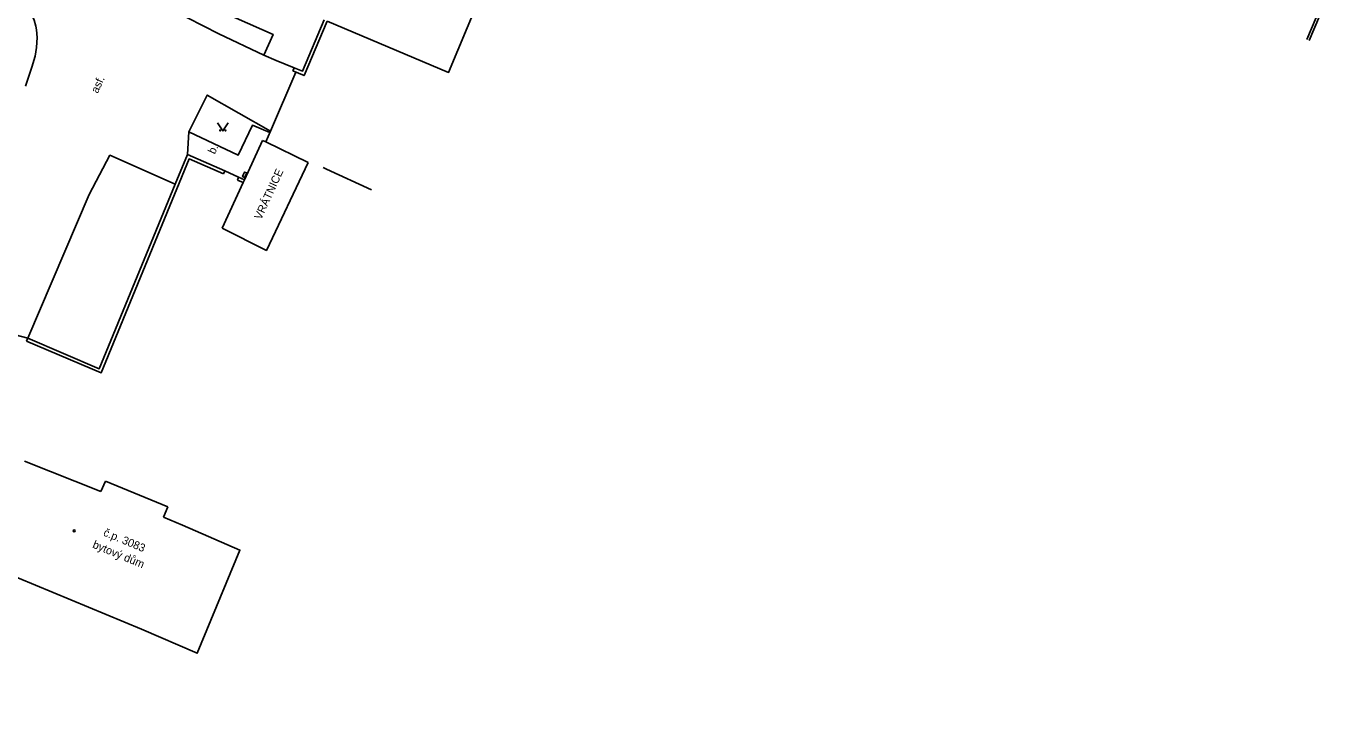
# Model space of a CAD drawing. Extents: x -584400 to -581602, y -1210894 to -1208793.
# Drawn here: x -582383.4 to -582261.2, y -1210133.9 to -1210069.5 of the extents above; entities that cross this region are included whole.
import ezdxf

# ---------------------------------------------------------------- set-up
doc = ezdxf.new("R2010")
doc.units = 0
for name, color, linetype in [('BUDOVY_MĚŘ', 7, 'Continuous'), ('BUDOVY_NEMĚŘ', 7, 'Continuous'), ('OBVOD_PILÍŘE', 7, 'Continuous'), ('POMOC_POPIS', 7, 'Continuous'), ('ROZHRANÍ_PLOCH', 7, 'Continuous'), ('ZN_BUDOV', 7, 'Continuous'), ('ZN_DOPLŇKOVÉ', 7, 'Continuous'), ('ZN_KULTUR', 7, 'Continuous'), ('Č_POPIS_ORIENT', 7, 'Continuous')]:
    doc.layers.add(name, color=color, linetype=linetype)

msp = doc.modelspace()

# ---------------------------------------------------------------- linework, layer by layer
at = {"layer": 'BUDOVY_MĚŘ'}
for points in [[(-582361.22, -1210080.25), (-582362.91, -1210083.93), (-582363.04, -1210084.2), (-582365, -1210088.47)], [(-582361.22, -1210080.25), (-582360.91, -1210080.39), (-582356.96, -1210082.32)], [(-582355.54, -1210082.79), (-582355.23, -1210082.93), (-582351, -1210084.89)], [(-582383.54, -1210110.3), (-582376.37, -1210113.14)], [(-582376.37, -1210113.14), (-582375.95, -1210112.16)], [(-582375.95, -1210112.16), (-582370.11, -1210114.57)], [(-582370.11, -1210114.57), (-582370.51, -1210115.56)], [(-582372.58, -1210126.03), (-582367.34, -1210128.3), (-582363.35, -1210118.64), (-582368.72, -1210116.31)], [(-582370.51, -1210115.56), (-582368.72, -1210116.31)], [(-582372.58, -1210126.03), (-582387.5, -1210119.87)]]:
    msp.add_lwpolyline(points, dxfattribs=at)
at = {"layer": 'BUDOVY_NEMĚŘ'}
for points in [[(-582324.28, -1210040.6), (-582328.11, -1210050.04), (-582332.42, -1210048.24), (-582334.79, -1210053.83), (-582335.37, -1210053.69), (-582343.78, -1210073.88), (-582355.17, -1210069.06)], [(-582365, -1210088.47), (-582360.86, -1210090.55), (-582356.96, -1210082.32)]]:
    msp.add_lwpolyline(points, dxfattribs=at)
at = {"layer": 'OBVOD_PILÍŘE'}
msp.add_lwpolyline([(-582363, -1210083.42), (-582362.9, -1210083.21), (-582362.7, -1210083.3), (-582362.9, -1210083.73), (-582363.1, -1210083.63), (-582363, -1210083.42)], dxfattribs=at)
at = {"layer": 'ROZHRANÍ_PLOCH'}
for points in [[(-582411.02, -1210050.39), (-582390.83, -1210062.64), (-582385.16, -1210066.13), (-582384.54, -1210066.56), (-582383.97, -1210067.05), (-582383.46, -1210067.6), (-582383.19, -1210067.95), (-582382.88, -1210068.44), (-582382.64, -1210068.97), (-582382.47, -1210069.53), (-582382.41, -1210069.88), (-582382.35, -1210070.59), (-582382.4, -1210071.54), (-582382.54, -1210072.35), (-582382.85, -1210073.38), (-582383.44, -1210075.16)], [(-582370.87, -1210063.26), (-582370.75, -1210064.68), (-582370.7, -1210065.22), (-582370.62, -1210065.6), (-582370.35, -1210066.42), (-582370.04, -1210067.13), (-582369.81, -1210067.51), (-582369.55, -1210067.81), (-582369.04, -1210068.25), (-582368.24, -1210068.77), (-582365.31, -1210070.26), (-582361.09, -1210072.27)], [(-582368.46, -1210064.37), (-582368.74, -1210064.24), (-582369.56, -1210066.17), (-582360.24, -1210070.32), (-582361.09, -1210072.27)], [(-582361.09, -1210072.27), (-582359.94, -1210072.77), (-582358.26, -1210073.45)], [(-582360.48, -1210079.38), (-582366.4, -1210076), (-582368.14, -1210079.45), (-582368.27, -1210081.58)], [(-582360.53, -1210079.52), (-582362.17, -1210078.82), (-582363.52, -1210081.63), (-582368.14, -1210079.45)], [(-582383.22, -1210098.77), (-582387.52, -1210097.64), (-582402.79, -1210133.89)]]:
    msp.add_lwpolyline(points, dxfattribs=at)
at = {"layer": 'ZN_BUDOV'}
msp.add_circle((-582378.87, -1210116.83), 0.0875, dxfattribs=at)
at = {"layer": 'ZN_DOPLŇKOVÉ'}
for points in [[(-582263.35, -1210070.79), (-582261.51, -1210066.41), (-582324.1, -1210040.05), (-582324.28, -1210040.6)], [(-582293.65, -1210052.61), (-582261.18, -1210066.28), (-582263.12, -1210070.89)], [(-582358.38, -1210073.72), (-582358.26, -1210073.45), (-582357.49, -1210073.77), (-582355.44, -1210068.95)], [(-582355.17, -1210069.06), (-582357.33, -1210074.17), (-582358.38, -1210073.72)], [(-582358.1, -1210073.84), (-582360.48, -1210079.38)], [(-582360.91, -1210080.39), (-582360.48, -1210079.38)], [(-582364.89, -1210083.39), (-582368.11, -1210081.98), (-582376.36, -1210102.04), (-582383.33, -1210099.05)], [(-582369.41, -1210084.36), (-582375.52, -1210081.64), (-582377.48, -1210085.32), (-582383.22, -1210098.77)], [(-582369.41, -1210084.36), (-582368.27, -1210081.58), (-582364.77, -1210083.1), (-582364.89, -1210083.39)], [(-582363.46, -1210083.69), (-582364.77, -1210083.1)], [(-582383.33, -1210099.05), (-582383.22, -1210098.77), (-582376.52, -1210101.64), (-582369.41, -1210084.36)], [(-582363.58, -1210083.96), (-582363.46, -1210083.69), (-582362.91, -1210083.93)], [(-582363.58, -1210083.96), (-582363.04, -1210084.2)]]:
    msp.add_lwpolyline(points, dxfattribs=at)
at = {"layer": 'ZN_KULTUR'}
msp.add_lwpolyline([(-582365.44, -1210078.61), (-582364.94, -1210079.36), (-582364.44, -1210078.61)], dxfattribs=at)
for centre in [(-582365.19, -1210079.31), (-582364.69, -1210079.31)]:
    msp.add_circle(centre, 0.05, dxfattribs=at)

# ---------------------------------------------------------------- texts
at = {"layer": 'POMOC_POPIS'}
for s, rotation, p in [('asf.', 65.2466, (-582376.67, -1210075.89)), ('b.', 65.2466, (-582365.7, -1210081.59)), ('VRÁTNICE', 65.3546, (-582361.36, -1210087.74)), ('bytový dům', 337.58, (-582377.22, -1210118.39))]:
    msp.add_text(s, height=0.75, rotation=rotation, dxfattribs=at).set_placement(p)
at = {"layer": 'Č_POPIS_ORIENT'}
msp.add_text('č.p. 3083', height=0.75, rotation=337.32, dxfattribs=at).set_placement((-582376.21, -1210117.25))

doc.saveas('drawing.dxf')
